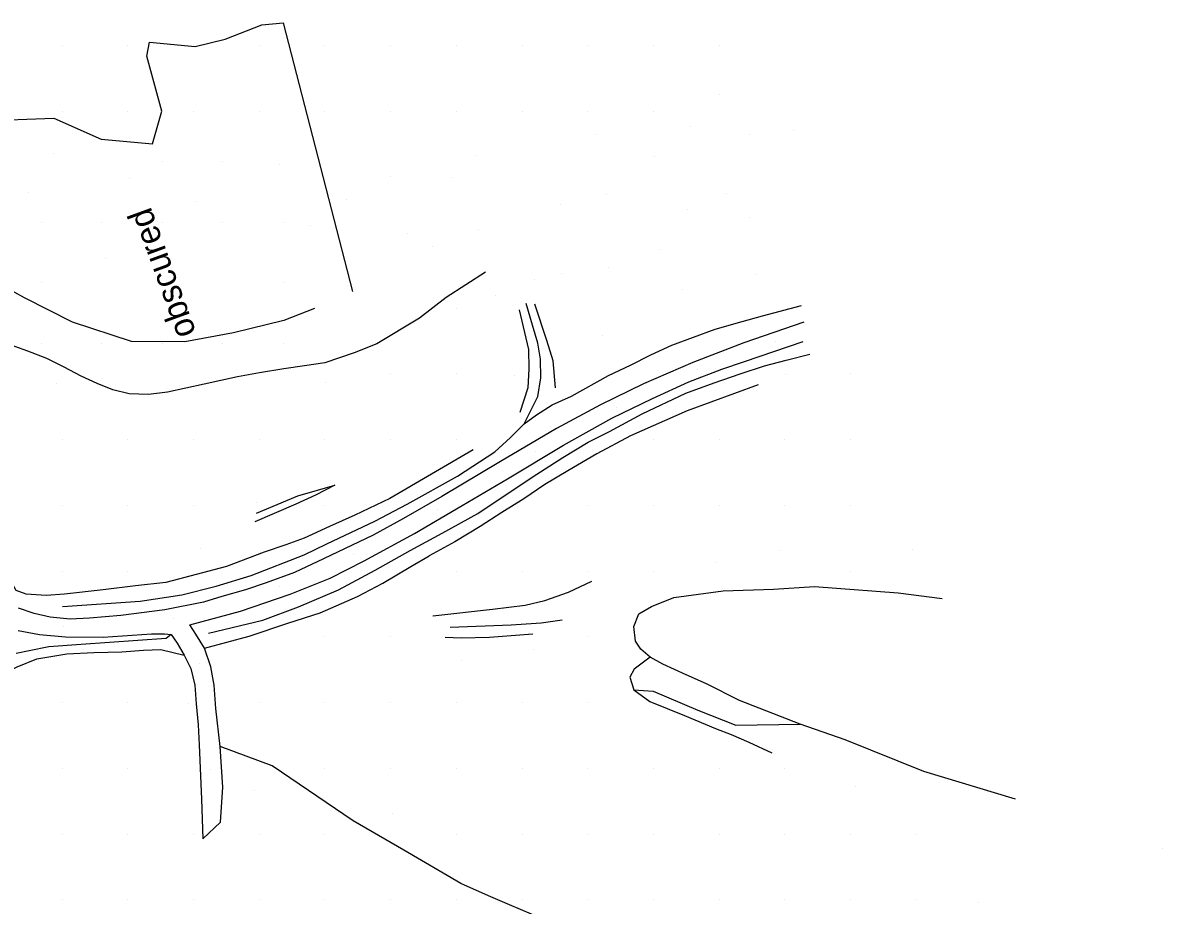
# Model space of a CAD drawing. Extents: x 524772 to 528246, y 273285 to 283088.
# Drawn here: x 527001.3 to 527170.4, y 276855.6 to 276986.6 of the extents above; entities that cross this region are included whole.
import ezdxf

# ---------------------------------------------------------------- set-up
doc = ezdxf.new("R2010")
doc.units = 0
for name, color, linetype in [('Old_Level_12', 7, 'Continuous'), ('PH Exist DTM Breakline', 7, 'Continuous'), ('PH Exist DTM Point', 7, 'Continuous')]:
    doc.layers.add(name, color=color, linetype=linetype)

msp = doc.modelspace()

# ---------------------------------------------------------------- linework, layer by layer
at = {"layer": 'Old_Level_12'}
for points in [[(526995.18, 276972.01), (527005.91, 276972.39), (527012.94, 276969.27), (527020.55, 276968.6), (527021.91, 276973.47), (527019.68, 276981.61), (527020.09, 276983.66), (527026.89, 276983.05), (527031.33, 276984.15), (527036.79, 276986.26), (527039.94, 276986.56), (527050.21, 276946.68)], [(527044.6, 276944.15), (527040.02, 276942.39), (527032.56, 276940.54), (527025.35, 276939.23), (527017.43, 276939.26), (527008.68, 276942.12), (527001.53, 276945.74), (526994.33, 276949.7)]]:
    msp.add_lwpolyline(points, dxfattribs=at)
at = {"layer": 'PH Exist DTM Breakline'}
for points in [[(527007.5, 276901.8), (527004.75, 276901.57), (527001.8, 276901.77), (527000.32, 276902.32), (526999.33, 276904.04), (526998.56, 276908.14), (526997.91, 276911.9), (526996.95, 276915.14), (526995.69, 276917.27), (526994.51, 276919.41), (526993.31, 276923.61), (526992.13, 276927.8), (526990.87, 276932.25), (526989.47, 276935.96), (526987.34, 276940.07), (526984.9, 276944.12), (526980.76, 276950.79), (526971.67, 276968.51), (526968.45, 276973.63)], [(527069.97, 276949.57), (527064.15, 276945.82), (527060.16, 276942.74), (527053.84, 276938.93), (527050.46, 276937.58), (527046.14, 276936.1), (527043.13, 276935.65), (527040.02, 276935.22), (527036.44, 276934.6), (527033.14, 276934.05), (527028.19, 276932.93), (527022.77, 276931.73), (527019.93, 276931.41), (527017.09, 276931.5), (527014.63, 276932.09), (527012.34, 276933.04), (527009.97, 276934.15), (527007.41, 276935.48), (527004.85, 276936.73), (527002.04, 276937.82), (526998.16, 276939.22), (526995.74, 276940.07), (526993, 276940.98), (526987.87, 276942.86)], [(527007.2, 276899.95), (527018.72, 276900.75), (527024.88, 276901.7), (527029.99, 276902.97), (527035.2, 276904.53), (527043.08, 276907.6), (527046.43, 276909.26), (527053.54, 276912.6), (527058.33, 276915.15), (527065.81, 276919.31), (527071.34, 276922.91), (527073.69, 276925.02), (527075.72, 276927.06), (527077.55, 276928.41), (527079.85, 276929.86), (527082.74, 276931.18), (527088.24, 276934.23), (527091.5, 276935.78), (527094.5, 276937.28), (527097.64, 276938.71), (527100.84, 276939.93), (527104.08, 276941.09), (527108.07, 276942.25), (527111.08, 276943.08), (527116.91, 276944.6)], [(527074.99, 276943.95), (527076.38, 276938.09), (527076.43, 276935.19), (527076.26, 276932.4), (527075.06, 276928.73)], [(527075.72, 276927.06), (527077.76, 276931.13), (527078.19, 276933.89), (527078.12, 276936.66), (527077.73, 276939.01), (527076.95, 276941.7), (527076.02, 276944.91)], [(527080.35, 276932.4), (527080.04, 276936.4), (527079.07, 276939.41), (527077.32, 276944.83)], [(527117.24, 276942.13), (527108.34, 276939.07), (527100.74, 276936.17), (527093.42, 276932.97), (527087.04, 276929.85), (527080.52, 276926.36), (527072.22, 276921.45), (527063.48, 276916.27), (527057.8, 276912.99), (527053.3, 276910.52), (527045.93, 276907.04), (527041.6, 276904.99), (527037.43, 276903.47), (527034.35, 276902.4), (527030.81, 276901.43), (527028.1, 276900.61), (527022.35, 276899.43), (527015.85, 276898.62), (527011.17, 276898.23), (527008.3, 276898.07), (527005.34, 276898.36), (527002.97, 276898.9), (527000.63, 276899.7)], [(527000.6, 276896.39), (527003.78, 276895.78), (527007.62, 276895.46), (527013.2, 276895.41), (527020.37, 276895.87), (527022.34, 276895.91), (527023.3, 276895.77), (527024.19, 276894.53), (527025.23, 276892.73), (527026.23, 276890.76), (527026.84, 276888.29), (527027.04, 276885.5), (527027.33, 276882.4), (527027.48, 276879.43), (527027.83, 276871.36), (527028.03, 276865.5), (527030.63, 276867.97), (527030.97, 276873.14), (527030.61, 276879.2), (527029.96, 276884.82), (527029.71, 276888.27), (527029.22, 276891), (527028.25, 276893.75), (527026.98, 276895.83), (527026.08, 276897.22), (527033.6, 276899.24), (527040.99, 276901.78), (527046.93, 276904.14), (527051.96, 276906.72), (527059.43, 276910.76), (527066.49, 276914.95), (527073.23, 276918.91), (527081.57, 276923.91), (527088.72, 276927.87), (527094.75, 276930.83), (527100.18, 276933.27), (527105.06, 276935.18), (527108.41, 276936.31), (527117.15, 276939.27)], [(527028.84, 276895.97), (527036.92, 276897.9), (527042.22, 276899.89), (527048.17, 276902.42), (527053.58, 276905.36), (527058.81, 276908.27), (527063.52, 276910.83), (527068.84, 276913.73), (527076.88, 276919.12), (527081.45, 276922.06), (527085.23, 276924.35), (527088.37, 276925.93), (527093.23, 276928.52), (527099.71, 276931.59), (527103.9, 276933.14), (527107.76, 276934.46), (527111.4, 276935.66), (527114.59, 276936.5), (527118.11, 276937.41)], [(527110.47, 276932.85), (527099.93, 276928.99), (527091.5, 276925.25), (527086.49, 276922.62), (527082.18, 276920.07), (527078.8, 276918.03), (527075.69, 276915.94), (527072.39, 276913.91), (527069.2, 276911.83), (527065.42, 276909.53), (527061.62, 276907.46)], [(527068.14, 276923.2), (527055.78, 276915.97), (527050.6, 276913.51), (527046.83, 276911.82), (527043.07, 276910.07), (527040.34, 276909.11), (527037.14, 276908.01), (527031.55, 276905.9), (527022.54, 276903.5), (527018.01, 276903.01), (527013.22, 276902.44), (527007.5, 276901.8)], [(527035.98, 276913.78), (527042.12, 276916.36), (527047.62, 276917.97), (527044.74, 276916.49), (527041.84, 276915.13), (527035.72, 276912.53)], [(527028.25, 276893.75), (527034.87, 276895.57), (527040.65, 276897.46), (527045.43, 276899.02), (527050.99, 276901.44), (527054.75, 276903.4), (527058.91, 276905.87), (527061.62, 276907.46)], [(527062.17, 276898.57), (527071.03, 276899.54), (527075.86, 276900.13), (527078.78, 276900.86), (527082.3, 276902.1), (527085.75, 276903.71)], [(527148.67, 276871.34), (527135.05, 276875.49), (527123.37, 276880.17), (527116.69, 276882.5), (527107.69, 276886.01), (527102.8, 276888.45), (527099.78, 276889.83), (527096.3, 276891.41), (527094.43, 276892.45), (527093.04, 276893.6), (527092.25, 276894.82), (527092.01, 276897), (527092.74, 276898.85), (527094.64, 276899.96), (527097.94, 276901.26), (527105.27, 276902.26), (527112.72, 276902.54), (527118.83, 276902.9), (527131.25, 276902), (527137.75, 276901.15)], [(527064.75, 276896.9), (527073.8, 276897.24), (527078.23, 276897.52), (527081.34, 276897.95)], [(527023.3, 276895.77), (527022.58, 276895.19), (527009.96, 276894.31), (527005.16, 276893.96), (527002.24, 276893.38), (527000.29, 276892.98)], [(527076.98, 276895.85), (527070.55, 276895.34), (527066.34, 276895.23), (527063.97, 276895.36)], [(526998.58, 276857.11), (526998.54, 276860.33), (526997.78, 276863.23), (526996.93, 276866.8), (526996.45, 276871.7), (526996.21, 276877.62), (526996.33, 276880.65), (526996.57, 276883.4), (526996.94, 276886.26), (526997.38, 276888.6), (526998.47, 276889.97), (527000.47, 276891.01), (527003.38, 276892.18), (527007.81, 276892.94), (527011.84, 276893.14), (527015.97, 276893.21), (527019.22, 276893.45), (527021.8, 276893.58), (527025.23, 276892.73)], [(527094.43, 276892.45), (527092.05, 276890.63), (527091.41, 276889.47), (527091.99, 276887.58), (527094.35, 276885.83), (527099.53, 276883.76), (527104.11, 276881.85), (527106.44, 276880.96), (527109.08, 276879.84), (527112.5, 276878.26)], [(527091.99, 276887.58), (527094.85, 276887.39), (527101.5, 276884.57), (527107.12, 276882.36), (527116.69, 276882.5)], [(527123.19, 276826.08), (527113.62, 276833.25), (527103.12, 276839.92), (527097.42, 276843.59), (527094.46, 276845.25), (527091.59, 276847.01), (527087.79, 276849.08), (527083.28, 276851.39), (527078.45, 276853.63), (527073.53, 276855.69), (527070.42, 276857.02), (527066.3, 276858.85), (527057.85, 276863.8), (527050.32, 276868.15), (527038.33, 276876.31), (527030.61, 276879.2)]]:
    msp.add_lwpolyline(points, dxfattribs=at)
at = {"layer": 'PH Exist DTM Point'}
for p, q in [((527007.13, 276983.22), (527007.13, 276983.22)), ((527016.88, 276983.22), (527016.88, 276983.22)), ((527026.64, 276983.22), (527026.64, 276983.22)), ((527036.39, 276983.22), (527036.39, 276983.22)), ((527046.14, 276983.22), (527046.14, 276983.22)), ((527055.9, 276983.22), (527055.9, 276983.22)), ((527065.65, 276983.22), (527065.65, 276983.22)), ((527075.4, 276983.22), (527075.4, 276983.22)), ((527085.16, 276983.22), (527085.16, 276983.22)), ((527094.91, 276983.22), (527094.91, 276983.22)), ((527104.67, 276983.22), (527104.67, 276983.22)), ((527104.77, 276975.98), (527104.77, 276975.98)), ((527007.13, 276973.47), (527007.13, 276973.47)), ((527016.88, 276973.47), (527016.88, 276973.47)), ((527026.64, 276973.47), (527026.64, 276973.47)), ((527036.39, 276973.47), (527036.39, 276973.47)), ((527046.14, 276973.47), (527046.14, 276973.47)), ((527055.9, 276973.47), (527055.9, 276973.47)), ((527065.65, 276973.47), (527065.65, 276973.47)), ((527075.4, 276973.47), (527075.4, 276973.47)), ((527085.14, 276973.46), (527085.14, 276973.46)), ((527094.93, 276973.47), (527094.93, 276973.47)), ((527100.41, 276971.17), (527100.41, 276971.17)), ((527086.44, 276970.04), (527086.44, 276970.04)), ((527109.2, 276969.97), (527109.2, 276969.97)), ((527115.76, 276970.52), (527115.76, 276970.52)), ((527005.87, 276967.1), (527005.87, 276967.1)), ((527022, 276966), (527022, 276966)), ((527031, 276966), (527031, 276966)), ((527068.42, 276966.81), (527068.42, 276966.81)), ((527095.07, 276966.65), (527095.07, 276966.65)), ((527039.39, 276965.46), (527039.39, 276965.46)), ((527017.08, 276963.42), (527017.08, 276963.42)), ((527055.88, 276963.69), (527055.88, 276963.69)), ((527064.94, 276963.62), (527064.94, 276963.62)), ((527002.08, 276961.39), (527002.08, 276961.39)), ((527087.88, 276961.15), (527087.88, 276961.15)), ((527105.81, 276961.24), (527105.81, 276961.24)), ((527026.94, 276960.05), (527026.94, 276960.05)), ((527049.3, 276960.28), (527049.3, 276960.28)), ((527081.06, 276959.53), (527081.06, 276959.53)), ((527100.02, 276958.84), (527100.02, 276958.84)), ((527109.19, 276957.6), (527109.19, 276957.6)), ((527004, 276957), (527004, 276957)), ((527013.01, 276957), (527013.01, 276957)), ((527022, 276957), (527022, 276957)), ((527031, 276957), (527031, 276957)), ((527040, 276957), (527040, 276957)), ((527044.01, 276956.41), (527044.01, 276956.41)), ((527069, 276955.92), (527069, 276955.92)), ((527058.38, 276955.3), (527058.38, 276955.3)), ((527062.16, 276953.35), (527062.16, 276953.35)), ((527095.9, 276952.92), (527095.9, 276952.92)), ((527013.59, 276951.57), (527013.59, 276951.57)), ((527081.25, 276949.33), (527081.25, 276949.33)), ((527088.3, 276950.28), (527088.3, 276950.28)), ((527110.05, 276949.25), (527110.05, 276949.25)), ((527004, 276948), (527004, 276948)), ((527040, 276948), (527040, 276948)), ((527077.26, 276948.43), (527077.26, 276948.43)), ((527071.44, 276946.16), (527071.44, 276946.16)), ((527099.25, 276947.02), (527099.25, 276947.02)), ((527065.65, 276944.21), (527065.65, 276944.21)), ((527004, 276939), (527004, 276939)), ((527013, 276939), (527013, 276939)), ((527022, 276939), (527022, 276939)), ((527031, 276939), (527031, 276939)), ((527040, 276939), (527040, 276939)), ((527087.32, 276940.13), (527087.32, 276940.13)), ((527113.1, 276939.28), (527113.1, 276939.28)), ((527055.9, 276934.45), (527055.9, 276934.45)), ((527065.65, 276934.45), (527065.65, 276934.45)), ((527074.26, 276934.22), (527074.26, 276934.22)), ((527101.46, 276935.09), (527101.46, 276935.09)), ((527114.44, 276934.44), (527114.44, 276934.44)), ((527124.17, 276934.45), (527124.17, 276934.45)), ((527006.33, 276933.04), (527006.33, 276933.04)), ((527046.17, 276933.14), (527046.17, 276933.14)), ((527089.38, 276929.48), (527089.38, 276929.48)), ((527007.13, 276924.7), (527007.13, 276924.7)), ((527016.88, 276924.7), (527016.88, 276924.7)), ((527026.64, 276924.7), (527026.64, 276924.7)), ((527036.39, 276924.7), (527036.39, 276924.7)), ((527046.14, 276924.7), (527046.14, 276924.7)), ((527055.9, 276924.7), (527055.9, 276924.7)), ((527065.65, 276924.7), (527065.65, 276924.7)), ((527094.91, 276924.7), (527094.91, 276924.7)), ((527104.67, 276924.7), (527104.67, 276924.7)), ((527114.42, 276924.7), (527114.42, 276924.7)), ((527124.16, 276924.68), (527124.16, 276924.68)), ((527077.34, 276922.9), (527077.34, 276922.9)), ((527007.11, 276914.94), (527007.11, 276914.94)), ((527016.88, 276914.95), (527016.88, 276914.95)), ((527026.64, 276914.95), (527026.64, 276914.95)), ((527036, 276915.38), (527036, 276915.38)), ((527046.14, 276914.95), (527046.14, 276914.95)), ((527085.16, 276914.95), (527085.16, 276914.95)), ((527094.91, 276914.95), (527094.91, 276914.95)), ((527104.67, 276914.95), (527104.67, 276914.95)), ((527114.42, 276914.95), (527114.42, 276914.95)), ((527124.17, 276914.95), (527124.17, 276914.95)), ((527062.86, 276914.36), (527062.86, 276914.36)), ((527027.68, 276908.51), (527027.68, 276908.51)), ((527113.76, 276908.25), (527113.76, 276908.25)), ((527133.35, 276908.36), (527133.35, 276908.36)), ((527050.45, 276907.63), (527050.45, 276907.63)), ((527104.24, 276906.44), (527104.24, 276906.44)), ((527007.11, 276905.19), (527007.11, 276905.19)), ((527016.88, 276905.19), (527016.88, 276905.19)), ((527065.65, 276905.19), (527065.65, 276905.19)), ((527075.4, 276905.19), (527075.4, 276905.19)), ((527085.16, 276905.19), (527085.16, 276905.19)), ((527094.91, 276905.19), (527094.91, 276905.19)), ((527124.15, 276905.19), (527124.15, 276905.19)), ((527039.44, 276902.98), (527039.44, 276902.98)), ((527023.63, 276898.11), (527023.63, 276898.11)), ((527007.33, 276897.03), (527007.33, 276897.03)), ((527046.14, 276895.44), (527046.14, 276895.44)), ((527055.9, 276895.44), (527055.9, 276895.44)), ((527085.16, 276895.44), (527085.16, 276895.44)), ((527077.1, 276893.59), (527077.1, 276893.59)), ((527027.54, 276891.48), (527027.54, 276891.48)), ((527066.47, 276892), (527066.47, 276892)), ((527007.13, 276885.68), (527007.13, 276885.68)), ((527016.88, 276885.68), (527016.88, 276885.68)), ((527025.89, 276885.53), (527025.89, 276885.53)), ((527036.39, 276885.68), (527036.39, 276885.68)), ((527046.14, 276885.68), (527046.14, 276885.68)), ((527055.9, 276885.68), (527055.9, 276885.68)), ((527065.65, 276885.68), (527065.65, 276885.68)), ((527075.4, 276885.68), (527075.4, 276885.68)), ((527085.16, 276885.68), (527085.16, 276885.68)), ((527007.13, 276875.93), (527007.13, 276875.93)), ((527016.88, 276875.93), (527016.88, 276875.93)), ((527029.19, 276875.72), (527029.19, 276875.72)), ((527046.14, 276875.93), (527046.14, 276875.93)), ((527055.9, 276875.93), (527055.9, 276875.93)), ((527065.65, 276875.93), (527065.65, 276875.93)), ((527075.4, 276875.93), (527075.4, 276875.93)), ((527085.16, 276875.93), (527085.16, 276875.93)), ((527094.91, 276875.93), (527094.91, 276875.93)), ((527104.67, 276875.93), (527104.67, 276875.93)), ((527114.42, 276875.93), (527114.42, 276875.93)), ((527124.95, 276873.31), (527124.95, 276873.31)), ((527035.72, 276872.6), (527035.72, 276872.6)), ((527056.13, 276869.22), (527056.13, 276869.22)), ((527007.13, 276866.18), (527007.13, 276866.18)), ((527016.88, 276866.18), (527016.88, 276866.18)), ((527026.64, 276866.18), (527026.64, 276866.18)), ((527036.39, 276866.18), (527036.39, 276866.18)), ((527046.14, 276866.18), (527046.14, 276866.18)), ((527065.65, 276866.18), (527065.65, 276866.18)), ((527075.4, 276866.18), (527075.4, 276866.18)), ((527085.16, 276866.18), (527085.16, 276866.18)), ((527094.91, 276866.18), (527094.91, 276866.18)), ((527104.67, 276866.18), (527104.67, 276866.18)), ((527114.42, 276866.18), (527114.42, 276866.18)), ((527124.17, 276866.18), (527124.17, 276866.18)), ((527133.91, 276866.17), (527133.91, 276866.17)), ((527170.44, 276864.01), (527170.44, 276864.01)), ((527007.11, 276856.42), (527007.11, 276856.42)), ((527016.88, 276856.42), (527016.88, 276856.42)), ((527026.64, 276856.42), (527026.64, 276856.42)), ((527036.39, 276856.42), (527036.39, 276856.42)), ((527046.14, 276856.42), (527046.14, 276856.42)), ((527055.9, 276856.42), (527055.9, 276856.42)), ((527065.65, 276856.42), (527065.65, 276856.42)), ((527075.42, 276856.43), (527075.42, 276856.43)), ((527085.16, 276856.42), (527085.16, 276856.42)), ((527094.91, 276856.42), (527094.91, 276856.42)), ((527104.67, 276856.42), (527104.67, 276856.42)), ((527114.42, 276856.42), (527114.42, 276856.42)), ((527124.17, 276856.42), (527124.17, 276856.42)), ((527133.93, 276856.42), (527133.93, 276856.42)), ((527143.14, 276855.99), (527143.14, 276855.99))]:
    msp.add_line(p, q, dxfattribs=at)

# ---------------------------------------------------------------- texts
at = {"layer": 'Old_Level_12'}
msp.add_text('obscured', height=3.645, rotation=110, dxfattribs=at).set_placement((527027.07, 276940.56))

doc.saveas('drawing.dxf')
